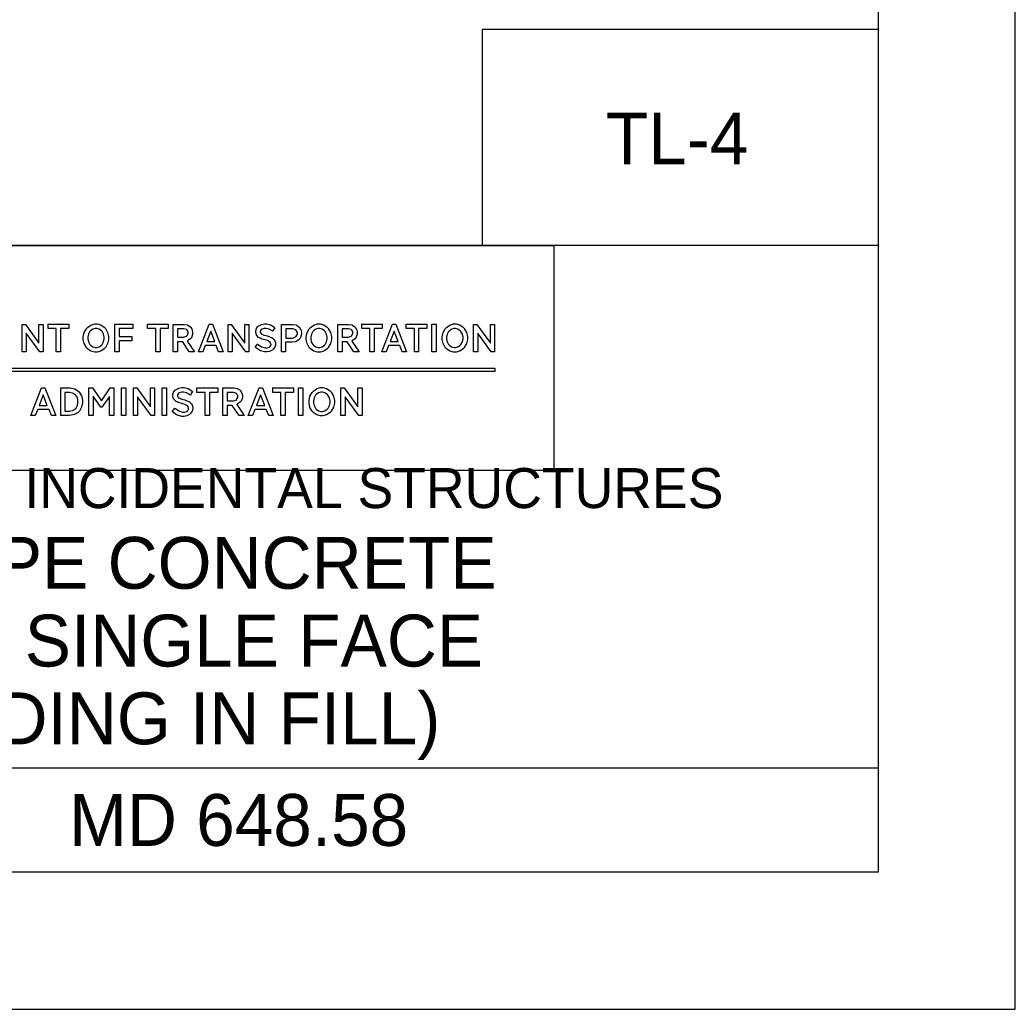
# Model space of a CAD drawing. Extents: x -53.2 to -44.7, y -19.5 to -8.5.
# Drawn here: x -47.035 to -44.731, y -19.549 to -17.259 of the extents above; entities that cross this region are included whole.
import ezdxf

# ---------------------------------------------------------------- set-up
doc = ezdxf.new("R2010")
doc.units = 0
for name, color, linetype in [('BORD-LINE', 7, 'Continuous'), ('Level 1', 7, 'Continuous'), ('MSHA-LOGO', 7, 'Continuous'), ('TTLB-TEXT', 7, 'Continuous'), ('USER-CLIP', 7, 'Continuous'), ('USER-LINE', 7, 'Continuous')]:
    doc.layers.add(name, color=color, linetype=linetype)

msp = doc.modelspace()

# ---------------------------------------------------------------- linework, layer by layer
at = {"layer": 'BORD-LINE'}
for p, q in [((-45.0478, -17.7814), (-49.5207, -17.7814)), ((-49.5207, -18.9904), (-45.0478, -18.9904))]:
    msp.add_line(p, q, dxfattribs=at)
msp.add_lwpolyline([(-52.422, -8.8791), (-45.0478, -8.8791), (-45.0478, -19.2322), (-52.422, -19.2322)], close=True, dxfattribs=at)
at = {"layer": 'Level 1'}
for p, q in [((-45.0478, -17.2814), (-45.9645, -17.2814)), ((-45.9645, -17.2814), (-45.9645, -17.7814))]:
    msp.add_line(p, q, dxfattribs=at)
at = {"layer": 'MSHA-LOGO'}
for points in [[(-46.9888, -18.0277), (-47.0202, -17.9842), (-47.0202, -18.0277), (-47.0297, -18.0277), (-47.0297, -17.9642), (-47.0221, -17.9642), (-46.9907, -18.0076), (-46.9907, -17.9642), (-46.9812, -17.9642), (-46.9812, -18.0277)], [(-46.9698, -17.9638), (-46.9217, -17.9638), (-46.9217, -17.974), (-46.9407, -17.974), (-46.9407, -18.0273), (-46.9505, -18.0273), (-46.9505, -17.974), (-46.9695, -17.974), (-46.9695, -17.9638)], [(-46.8795, -17.9727), (-46.8781, -17.9711), (-46.8702, -17.9656), (-46.8617, -17.9632), (-46.8589, -17.9632), (-46.8561, -17.9632), (-46.8476, -17.9654), (-46.8397, -17.9708), (-46.8383, -17.9724), (-46.8369, -17.9739), (-46.8319, -17.9828), (-46.8297, -17.9925), (-46.8297, -17.9957), (-46.8297, -17.9989), (-46.8319, -18.0085), (-46.8369, -18.0175), (-46.8383, -18.0191), (-46.8397, -18.0207), (-46.8476, -18.026), (-46.8561, -18.0283), (-46.8589, -18.0283), (-46.8617, -18.0283), (-46.8702, -18.026), (-46.8781, -18.0207), (-46.8795, -18.0191), (-46.8809, -18.0175), (-46.8858, -18.0087), (-46.888, -17.999), (-46.888, -17.9957), (-46.888, -17.9926), (-46.8858, -17.9831), (-46.8809, -17.9743)], [(-46.815, -17.9638), (-46.7731, -17.9638), (-46.7731, -17.974), (-46.8052, -17.974), (-46.8052, -17.9921), (-46.7754, -17.9921), (-46.7754, -18.0023), (-46.8052, -18.0023), (-46.8052, -18.0273), (-46.815, -18.0273)], [(-46.7394, -17.9638), (-46.6913, -17.9638), (-46.6913, -17.974), (-46.7103, -17.974), (-46.7103, -18.0273), (-46.7201, -18.0273), (-46.7201, -17.974), (-46.7391, -17.974), (-46.7391, -17.9638)], [(-46.6799, -18.0277), (-46.6799, -17.9642), (-46.6576, -17.9642), (-46.6548, -17.9642), (-46.6473, -17.9655), (-46.6465, -17.9658), (-46.6458, -17.966), (-46.64, -17.9699), (-46.6396, -17.9704), (-46.6392, -17.9709), (-46.6363, -17.9761), (-46.636, -17.9767), (-46.6358, -17.9772), (-46.635, -17.9825), (-46.635, -17.9842), (-46.635, -17.9871), (-46.6377, -17.9949), (-46.6383, -17.9957), (-46.6389, -17.9966), (-46.6465, -18.0023), (-46.6475, -18.0027), (-46.6304, -18.028), (-46.6426, -18.028), (-46.6579, -18.0046), (-46.67, -18.0046), (-46.67, -18.028), (-46.6799, -18.028)], [(-46.5967, -17.9638), (-46.5892, -17.9638), (-46.5644, -18.0273), (-46.5748, -18.0273), (-46.5804, -18.0132), (-46.6059, -18.0132), (-46.6115, -18.0273), (-46.6216, -18.0273)], [(-46.512, -18.0277), (-46.5434, -17.9842), (-46.5434, -18.0277), (-46.5529, -18.0277), (-46.5529, -17.9642), (-46.5454, -17.9642), (-46.514, -18.0076), (-46.514, -17.9642), (-46.5045, -17.9642), (-46.5045, -18.0277)], [(-46.4557, -18.0053), (-46.456, -18.0049), (-46.4601, -18.0022), (-46.4606, -18.002), (-46.4611, -18.0018), (-46.4668, -18.0002), (-46.4675, -18), (-46.4681, -17.9998), (-46.4744, -17.998), (-46.475, -17.9977), (-46.4757, -17.9975), (-46.4814, -17.9948), (-46.4819, -17.9944), (-46.4824, -17.9941), (-46.4865, -17.9897), (-46.4868, -17.9892), (-46.4871, -17.9886), (-46.4887, -17.9828), (-46.4887, -17.9809), (-46.4887, -17.9792), (-46.4872, -17.974), (-46.4836, -17.969), (-46.4825, -17.9681), (-46.4815, -17.9672), (-46.4754, -17.9641), (-46.4687, -17.9628), (-46.4665, -17.9628), (-46.4634, -17.9628), (-46.454, -17.9651), (-46.4459, -17.9705), (-46.4446, -17.9721), (-46.4498, -17.98), (-46.451, -17.9789), (-46.4577, -17.9751), (-46.4646, -17.9734), (-46.4668, -17.9734), (-46.469, -17.9734), (-46.4748, -17.975), (-46.4753, -17.9753), (-46.4759, -17.9757), (-46.4786, -17.9796), (-46.4786, -17.9809), (-46.4786, -17.9822), (-46.4764, -17.9855), (-46.476, -17.9859), (-46.4756, -17.9862), (-46.4701, -17.9887), (-46.4695, -17.9888), (-46.4688, -17.989), (-46.4617, -17.9909), (-46.4609, -17.9911), (-46.4602, -17.9914), (-46.4531, -17.9941), (-46.4524, -17.9944), (-46.4518, -17.9948), (-46.4463, -17.9994), (-46.4459, -18), (-46.4455, -18.0007), (-46.4433, -18.0071), (-46.4433, -18.0092), (-46.4433, -18.0111), (-46.4448, -18.0167), (-46.4484, -18.0218), (-46.4495, -18.0227), (-46.4505, -18.0236), (-46.4566, -18.0267), (-46.4628, -18.028), (-46.4649, -18.028), (-46.4685, -18.028), (-46.4781, -18.0253), (-46.4793, -18.0247), (-46.4804, -18.0241), (-46.4894, -18.0173), (-46.4901, -18.0165), (-46.4842, -18.0089), (-46.4829, -18.0104), (-46.4753, -18.0157), (-46.467, -18.0181), (-46.4642, -18.0181), (-46.4622, -18.0181), (-46.4568, -18.0165), (-46.4564, -18.0161), (-46.4559, -18.0158), (-46.4534, -18.0118), (-46.4534, -18.0105), (-46.4535, -18.01), (-46.4554, -18.0056)], [(-46.4295, -18.0277), (-46.4295, -17.9642), (-46.4066, -17.9642), (-46.4037, -17.9642), (-46.3956, -17.9655), (-46.3948, -17.9658), (-46.394, -17.9661), (-46.388, -17.9702), (-46.3876, -17.9707), (-46.3872, -17.9712), (-46.3842, -17.9767), (-46.384, -17.9773), (-46.3839, -17.9779), (-46.383, -17.9831), (-46.383, -17.9849), (-46.383, -17.9868), (-46.3841, -17.9919), (-46.3844, -17.9924), (-46.3846, -17.993), (-46.3879, -17.9985), (-46.3883, -17.999), (-46.3887, -17.9995), (-46.395, -18.0036), (-46.3958, -18.004), (-46.3966, -18.0043), (-46.4044, -18.0056), (-46.4069, -18.0056), (-46.42, -18.0056), (-46.42, -18.0273), (-46.4295, -18.0273)], [(-46.3634, -17.9727), (-46.362, -17.9711), (-46.3541, -17.9656), (-46.3456, -17.9632), (-46.3428, -17.9632), (-46.34, -17.9632), (-46.3315, -17.9654), (-46.3236, -17.9708), (-46.3222, -17.9724), (-46.3208, -17.9739), (-46.3158, -17.9828), (-46.3137, -17.9925), (-46.3137, -17.9957), (-46.3137, -17.9989), (-46.3158, -18.0085), (-46.3208, -18.0175), (-46.3222, -18.0191), (-46.3236, -18.0207), (-46.3315, -18.026), (-46.34, -18.0283), (-46.3428, -18.0283), (-46.3456, -18.0283), (-46.3541, -18.026), (-46.362, -18.0207), (-46.3634, -18.0191), (-46.3648, -18.0175), (-46.3698, -18.0087), (-46.3719, -17.999), (-46.3719, -17.9957), (-46.3718, -17.9934), (-46.3696, -17.9831), (-46.3648, -17.9743)], [(-46.2989, -18.0277), (-46.2989, -17.9642), (-46.2767, -17.9642), (-46.2739, -17.9642), (-46.2664, -17.9655), (-46.2656, -17.9658), (-46.2648, -17.966), (-46.2591, -17.9699), (-46.2587, -17.9704), (-46.2583, -17.9709), (-46.2554, -17.9761), (-46.2551, -17.9767), (-46.2549, -17.9772), (-46.2541, -17.9825), (-46.2541, -17.9842), (-46.2541, -17.9871), (-46.2568, -17.9949), (-46.2574, -17.9957), (-46.258, -17.9966), (-46.2656, -18.0023), (-46.2666, -18.0027), (-46.2495, -18.028), (-46.2616, -18.028), (-46.277, -18.0046), (-46.2891, -18.0046), (-46.2891, -18.028), (-46.2989, -18.028)], [(-46.244, -17.9638), (-46.1958, -17.9638), (-46.1958, -17.974), (-46.2148, -17.974), (-46.2148, -18.0273), (-46.2247, -18.0273), (-46.2247, -17.974), (-46.2436, -17.974), (-46.2436, -17.9638)], [(-46.172, -17.9638), (-46.1644, -17.9638), (-46.1396, -18.0273), (-46.15, -18.0273), (-46.1556, -18.0132), (-46.1815, -18.0132), (-46.187, -18.0273), (-46.1968, -18.0273)], [(-46.1409, -17.9638), (-46.0928, -17.9638), (-46.0928, -17.974), (-46.1118, -17.974), (-46.1118, -18.0273), (-46.1216, -18.0273), (-46.1216, -17.974), (-46.1406, -17.974), (-46.1406, -17.9638)], [(-46.0813, -17.9638), (-46.0715, -17.9638), (-46.0715, -18.0273), (-46.0813, -18.0273)], [(-46.0486, -17.9727), (-46.0472, -17.9711), (-46.0393, -17.9656), (-46.0308, -17.9632), (-46.028, -17.9632), (-46.0252, -17.9632), (-46.0167, -17.9654), (-46.0088, -17.9708), (-46.0074, -17.9724), (-46.006, -17.9739), (-46.001, -17.9828), (-45.9989, -17.9925), (-45.9989, -17.9957), (-45.9989, -17.9989), (-46.001, -18.0085), (-46.006, -18.0175), (-46.0074, -18.0191), (-46.0088, -18.0207), (-46.0167, -18.026), (-46.0252, -18.0283), (-46.028, -18.0283), (-46.0308, -18.0283), (-46.0393, -18.026), (-46.0472, -18.0207), (-46.0486, -18.0191), (-46.05, -18.0175), (-46.0549, -18.0087), (-46.0571, -17.999), (-46.0571, -17.9957), (-46.0571, -17.9926), (-46.0551, -17.9831), (-46.0501, -17.9743)], [(-45.9435, -18.0277), (-45.975, -17.9842), (-45.975, -18.0277), (-45.9844, -18.0277), (-45.9844, -17.9642), (-45.9769, -17.9642), (-45.9455, -18.0076), (-45.9455, -17.9642), (-45.936, -17.9642), (-45.936, -18.0277)], [(-46.872, -18.0115), (-46.8711, -18.0126), (-46.8659, -18.0163), (-46.8604, -18.0178), (-46.8585, -18.0178), (-46.8567, -18.0178), (-46.8512, -18.0163), (-46.846, -18.0126), (-46.8451, -18.0115), (-46.8442, -18.0105), (-46.841, -18.0046), (-46.8396, -17.9979), (-46.8396, -17.9957), (-46.8396, -17.9935), (-46.841, -17.9868), (-46.8442, -17.9809), (-46.8451, -17.98), (-46.846, -17.9789), (-46.8512, -17.9752), (-46.8567, -17.9737), (-46.8585, -17.9737), (-46.8604, -17.9737), (-46.8659, -17.9752), (-46.8711, -17.9789), (-46.872, -17.98), (-46.8729, -17.9809), (-46.8761, -17.9868), (-46.8775, -17.9935), (-46.8775, -17.9957), (-46.8775, -17.9979), (-46.8762, -18.0046), (-46.873, -18.0105)], [(-46.67, -17.9744), (-46.67, -17.9938), (-46.6573, -17.9938), (-46.6551, -17.9938), (-46.649, -17.9916), (-46.6484, -17.9911), (-46.648, -17.9907), (-46.6452, -17.9854), (-46.6452, -17.9836), (-46.6452, -17.9818), (-46.6476, -17.9771), (-46.6481, -17.9767), (-46.6486, -17.9763), (-46.6554, -17.9744), (-46.6576, -17.9744)], [(-46.6023, -18.004), (-46.5836, -18.004), (-46.5931, -17.98)], [(-46.4194, -17.9744), (-46.4194, -17.9957), (-46.4063, -17.9957), (-46.4037, -17.9957), (-46.396, -17.993), (-46.3925, -17.9869), (-46.3925, -17.9849), (-46.3925, -17.9829), (-46.3958, -17.977), (-46.4032, -17.9744), (-46.4056, -17.9744)], [(-46.3559, -18.0115), (-46.355, -18.0126), (-46.3498, -18.0163), (-46.3443, -18.0178), (-46.3425, -18.0178), (-46.3406, -18.0178), (-46.3352, -18.0163), (-46.33, -18.0126), (-46.3291, -18.0115), (-46.3282, -18.0105), (-46.3249, -18.0046), (-46.3235, -17.9979), (-46.3235, -17.9957), (-46.3235, -17.9935), (-46.3249, -17.9868), (-46.3282, -17.9809), (-46.3291, -17.98), (-46.33, -17.9789), (-46.3352, -17.9752), (-46.3406, -17.9737), (-46.3425, -17.9737), (-46.3443, -17.9737), (-46.3497, -17.9752), (-46.3549, -17.9789), (-46.3559, -17.98), (-46.3568, -17.9809), (-46.36, -17.9868), (-46.3615, -17.9935), (-46.3615, -17.9957), (-46.3615, -17.9979), (-46.3602, -18.0046), (-46.3569, -18.0105)], [(-46.2891, -17.9744), (-46.2891, -17.9938), (-46.2764, -17.9938), (-46.2742, -17.9938), (-46.2681, -17.9916), (-46.2675, -17.9911), (-46.267, -17.9907), (-46.2642, -17.9854), (-46.2642, -17.9836), (-46.2642, -17.9818), (-46.2667, -17.9771), (-46.2672, -17.9767), (-46.2677, -17.9763), (-46.2744, -17.9744), (-46.2767, -17.9744)], [(-46.1779, -18.004), (-46.1592, -18.004), (-46.1687, -17.98)], [(-46.0414, -18.0115), (-46.0405, -18.0126), (-46.0353, -18.0163), (-46.0298, -18.0178), (-46.028, -18.0178), (-46.0262, -18.0178), (-46.0207, -18.0163), (-46.0155, -18.0126), (-46.0146, -18.0115), (-46.0137, -18.0105), (-46.0104, -18.0046), (-46.009, -17.9979), (-46.009, -17.9957), (-46.009, -17.9935), (-46.0104, -17.9868), (-46.0137, -17.9809), (-46.0146, -17.98), (-46.0155, -17.9789), (-46.0207, -17.9752), (-46.0262, -17.9737), (-46.028, -17.9737), (-46.0298, -17.9737), (-46.0352, -17.9752), (-46.0404, -17.9789), (-46.0414, -17.98), (-46.0423, -17.9809), (-46.0455, -17.9868), (-46.0469, -17.9935), (-46.0469, -17.9957), (-46.0469, -17.9979), (-46.0455, -18.0046), (-46.0423, -18.0105)], [(-48.0516, -18.0656), (-45.935, -18.0656), (-45.935, -18.0735), (-48.0516, -18.0735)], [(-46.9844, -18.1111), (-46.9767, -18.1111), (-46.9515, -18.1754), (-46.962, -18.1754), (-46.9674, -18.1612), (-46.9936, -18.1612), (-46.9991, -18.1754), (-47.0093, -18.1754)], [(-46.9901, -18.1516), (-46.9713, -18.1516), (-46.9809, -18.1272)], [(-46.9403, -18.1111), (-46.9224, -18.1111), (-46.9187, -18.1111), (-46.9084, -18.1133), (-46.9074, -18.1137), (-46.9063, -18.1141), (-46.8978, -18.12), (-46.8972, -18.1208), (-46.8965, -18.1215), (-46.892, -18.1298), (-46.8917, -18.1307), (-46.8914, -18.1317), (-46.8901, -18.1399), (-46.8901, -18.1426), (-46.8901, -18.1459), (-46.8922, -18.1558), (-46.8971, -18.1648), (-46.8984, -18.1664), (-46.8998, -18.1679), (-46.9089, -18.1731), (-46.9197, -18.1754), (-46.9233, -18.1754), (-46.9403, -18.1754)], [(-46.9304, -18.1217), (-46.9304, -18.1651), (-46.9227, -18.1651), (-46.9202, -18.1651), (-46.9128, -18.1636), (-46.9067, -18.16), (-46.9058, -18.159), (-46.9048, -18.1579), (-46.9016, -18.1517), (-46.9003, -18.1449), (-46.9003, -18.1426), (-46.9003, -18.1403), (-46.9017, -18.1335), (-46.9059, -18.127), (-46.9128, -18.123), (-46.92, -18.1217), (-46.9224, -18.1217)], [(-46.8754, -18.1111), (-46.8665, -18.1111), (-46.846, -18.141), (-46.8262, -18.1111), (-46.8176, -18.1111), (-46.8176, -18.1754), (-46.8275, -18.1754), (-46.8275, -18.1307), (-46.8451, -18.1561), (-46.8476, -18.1561), (-46.8655, -18.1304), (-46.8655, -18.175), (-46.8754, -18.175)], [(-46.7997, -18.1111), (-46.7898, -18.1111), (-46.7898, -18.1754), (-46.7997, -18.1754)], [(-46.7307, -18.1754), (-46.7623, -18.1317), (-46.7623, -18.1754), (-46.7719, -18.1754), (-46.7719, -18.1111), (-46.7642, -18.1111), (-46.7326, -18.1551), (-46.7326, -18.1111), (-46.723, -18.1111), (-46.723, -18.1754)], [(-46.7054, -18.1111), (-46.6955, -18.1111), (-46.6955, -18.1754), (-46.7054, -18.1754)], [(-46.6467, -18.1532), (-46.647, -18.1529), (-46.6512, -18.1502), (-46.6518, -18.15), (-46.6523, -18.1498), (-46.6582, -18.1479), (-46.6588, -18.1477), (-46.6594, -18.1476), (-46.6658, -18.1457), (-46.6665, -18.1455), (-46.6671, -18.1452), (-46.6729, -18.1426), (-46.6735, -18.1423), (-46.6741, -18.1419), (-46.6783, -18.1374), (-46.6786, -18.1368), (-46.6789, -18.1363), (-46.6805, -18.1304), (-46.6805, -18.1285), (-46.6805, -18.1267), (-46.6789, -18.1214), (-46.6752, -18.1165), (-46.6741, -18.1156), (-46.6731, -18.1147), (-46.667, -18.1117), (-46.6601, -18.1105), (-46.6578, -18.1105), (-46.6547, -18.1105), (-46.6451, -18.1128), (-46.6368, -18.1183), (-46.6355, -18.1198), (-46.6409, -18.1278), (-46.6421, -18.1267), (-46.6488, -18.1228), (-46.6558, -18.1211), (-46.6582, -18.1211), (-46.6603, -18.1211), (-46.6662, -18.1227), (-46.6668, -18.123), (-46.6674, -18.1233), (-46.6703, -18.1274), (-46.6703, -18.1288), (-46.6703, -18.1301), (-46.6681, -18.1335), (-46.6677, -18.1339), (-46.6673, -18.1343), (-46.6618, -18.1367), (-46.661, -18.1368), (-46.6603, -18.137), (-46.6532, -18.1391), (-46.6524, -18.1394), (-46.6516, -18.1396), (-46.6444, -18.1423), (-46.6438, -18.1426), (-46.6431, -18.1429), (-46.6375, -18.1477), (-46.6371, -18.1484), (-46.6367, -18.149), (-46.6345, -18.1555), (-46.6345, -18.1577), (-46.6345, -18.1596), (-46.6361, -18.1653), (-46.6399, -18.1706), (-46.6409, -18.1715), (-46.6419, -18.1724), (-46.648, -18.1755), (-46.6544, -18.177), (-46.6566, -18.177), (-46.6602, -18.177), (-46.67, -18.1743), (-46.6712, -18.1738), (-46.6724, -18.1732), (-46.6815, -18.1662), (-46.6821, -18.1654), (-46.676, -18.1577), (-46.6748, -18.1592), (-46.6672, -18.1646), (-46.6585, -18.167), (-46.6556, -18.167), (-46.6536, -18.167), (-46.6481, -18.1654), (-46.6476, -18.1651), (-46.6471, -18.1647), (-46.6447, -18.1607), (-46.6447, -18.1593), (-46.6447, -18.1578), (-46.6463, -18.1535)], [(-46.6253, -18.1111), (-46.5767, -18.1111), (-46.5767, -18.1217), (-46.5958, -18.1217), (-46.5958, -18.1754), (-46.6057, -18.1754), (-46.6057, -18.1217), (-46.6249, -18.1217), (-46.6249, -18.1111)], [(-46.5652, -18.1754), (-46.5652, -18.1111), (-46.5425, -18.1111), (-46.5397, -18.1111), (-46.5321, -18.1125), (-46.5313, -18.1127), (-46.5305, -18.113), (-46.5247, -18.1167), (-46.5243, -18.1172), (-46.5239, -18.1177), (-46.5209, -18.1231), (-46.5208, -18.1237), (-46.5206, -18.1242), (-46.5198, -18.1293), (-46.5198, -18.131), (-46.5198, -18.1339), (-46.5228, -18.1418), (-46.5233, -18.1426), (-46.5239, -18.1434), (-46.5316, -18.1491), (-46.5326, -18.1493), (-46.5153, -18.175), (-46.5275, -18.175), (-46.5431, -18.1516), (-46.5553, -18.1516), (-46.5553, -18.175), (-46.5652, -18.175)], [(-46.5553, -18.1217), (-46.5553, -18.1413), (-46.5425, -18.1413), (-46.5403, -18.1413), (-46.5341, -18.1392), (-46.5335, -18.1388), (-46.533, -18.1383), (-46.5303, -18.1331), (-46.5303, -18.1314), (-46.5303, -18.1296), (-46.5328, -18.1247), (-46.5332, -18.1243), (-46.5337, -18.1239), (-46.5405, -18.1217), (-46.5428, -18.1217)], [(-46.4811, -18.1111), (-46.4735, -18.1111), (-46.4482, -18.1754), (-46.4588, -18.1754), (-46.4645, -18.1612), (-46.4907, -18.1612), (-46.4962, -18.1754), (-46.5064, -18.1754)], [(-46.4869, -18.1516), (-46.468, -18.1516), (-46.4776, -18.1272)], [(-46.4498, -18.1111), (-46.4013, -18.1111), (-46.4013, -18.1217), (-46.4204, -18.1217), (-46.4204, -18.1754), (-46.4304, -18.1754), (-46.4304, -18.1217), (-46.4495, -18.1217), (-46.4495, -18.1111)], [(-46.3898, -18.1111), (-46.3799, -18.1111), (-46.3799, -18.1754), (-46.3898, -18.1754)], [(-46.3569, -18.1201), (-46.3554, -18.1185), (-46.3473, -18.1129), (-46.3389, -18.1105), (-46.3361, -18.1105), (-46.3333, -18.1105), (-46.3248, -18.1128), (-46.3167, -18.1183), (-46.3153, -18.1198), (-46.314, -18.1213), (-46.309, -18.1303), (-46.3067, -18.14), (-46.3067, -18.1433), (-46.3067, -18.1464), (-46.3089, -18.156), (-46.3139, -18.1651), (-46.3153, -18.1667), (-46.3168, -18.1683), (-46.3249, -18.1737), (-46.3333, -18.176), (-46.3361, -18.176), (-46.339, -18.176), (-46.3476, -18.1736), (-46.3555, -18.1682), (-46.3569, -18.1667), (-46.3583, -18.1651), (-46.3633, -18.1562), (-46.3655, -18.1465), (-46.3655, -18.1433), (-46.3655, -18.1401), (-46.3633, -18.1306), (-46.3583, -18.1216)], [(-46.3495, -18.1593), (-46.3486, -18.1603), (-46.3433, -18.1639), (-46.3379, -18.1654), (-46.3361, -18.1654), (-46.3342, -18.1654), (-46.3286, -18.1639), (-46.3233, -18.1603), (-46.3224, -18.1593), (-46.3214, -18.1583), (-46.3182, -18.1522), (-46.3169, -18.1455), (-46.3169, -18.1433), (-46.3169, -18.141), (-46.3184, -18.1344), (-46.3217, -18.1282), (-46.3227, -18.1272), (-46.3236, -18.1261), (-46.3289, -18.1226), (-46.3343, -18.1211), (-46.3361, -18.1211), (-46.3379, -18.1211), (-46.3434, -18.1226), (-46.3486, -18.1261), (-46.3495, -18.1272), (-46.3504, -18.1282), (-46.3536, -18.1342), (-46.3549, -18.141), (-46.3549, -18.1433), (-46.3549, -18.1455), (-46.3536, -18.1522), (-46.3504, -18.1583)], [(-46.2505, -18.1754), (-46.2821, -18.1317), (-46.2821, -18.1754), (-46.2917, -18.1754), (-46.2917, -18.1111), (-46.284, -18.1111), (-46.2524, -18.1551), (-46.2524, -18.1111), (-46.2428, -18.1111), (-46.2428, -18.1754)]]:
    msp.add_lwpolyline(points, close=True, dxfattribs=at)
at = {"layer": 'USER-CLIP'}
msp.add_lwpolyline([(-44.7309, -8.5491), (-53.2309, -8.5491), (-53.2309, -19.5491), (-44.7309, -19.5491)], close=True, dxfattribs=at)
at = {"layer": 'USER-LINE'}
msp.add_lwpolyline([(-45.7987, -18.3022), (-48.7699, -18.3022), (-48.7699, -17.7814), (-45.7987, -17.7814)], close=True, dxfattribs=at)

# ---------------------------------------------------------------- texts
at = {"layer": 'BORD-LINE'}
msp.add_text('HDVBARREIRA', height=6e-12, rotation=180, dxfattribs=at).set_placement((-45.0478, -17.7814))
at = {"layer": 'TTLB-TEXT'}
for s, height, p in [('TL-4', 0.12, (-45.6782, -17.5937)), ('STANDARDS FOR HIGHWAYS AND INCIDENTAL STRUCTURES', 0.09269, (-49.1249, -18.3894)), ('42 INCH SINGLE SLOPE CONCRETE', 0.12, (-48.7046, -18.5761)), ('TRAFFIC BARRIER SINGLE FACE', 0.12, (-48.5035, -18.7561)), ('TYPE 2 (FREE STANDING IN FILL)', 0.12, (-48.6382, -18.9361)), ('MD 648.58', 0.12, (-46.9208, -19.1713))]:
    msp.add_text(s, height=height, dxfattribs=at).set_placement(p)

doc.saveas('drawing.dxf')
